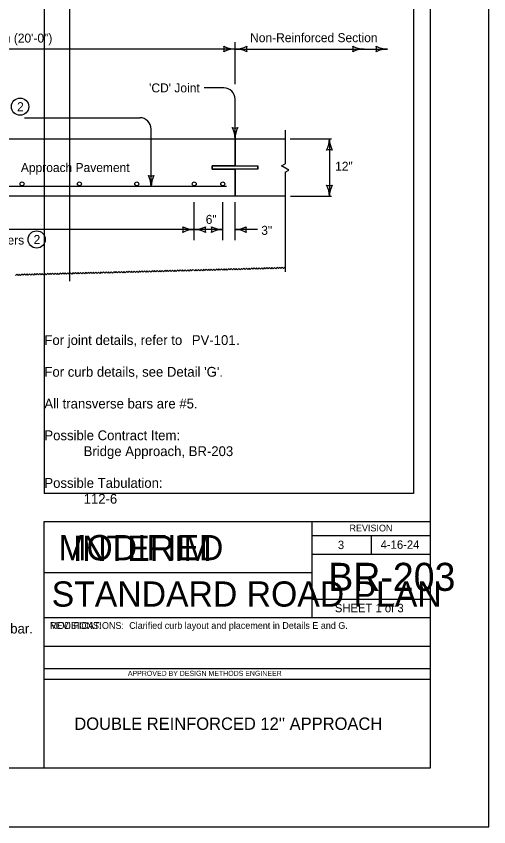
# Model space of a CAD drawing. Extents: x -2135039 to -2124495, y -2139046 to -2132546.
# Drawn here: x -2132538 to -2131695, y -2135130 to -2133685 of the extents above; entities that cross this region are included whole.
import ezdxf

# ---------------------------------------------------------------- set-up
doc = ezdxf.new("R2010")
doc.units = 0
for name, color, linetype in [('Barrier', 7, 'Continuous'), ('BridgeSuperStructureExisting', 7, 'Continuous'), ('Dimension', 7, 'Continuous'), ('dsnAlignmentCurveData', 7, 'Continuous'), ('dsnAlignmentStation', 7, 'Continuous'), ('dsnAlignmentTic', 7, 'Continuous'), ('dsnCellElements', 7, 'Continuous'), ('DsnShtPlotIdentification', 7, 'Continuous'), ('dsnStdLabel', 7, 'Continuous'), ('dsnStdLineWork', 7, 'Continuous'), ('dsnTextFinalPlan', 7, 'Continuous'), ('PhoEdgeShoulderPaved', 7, 'Continuous')]:
    doc.layers.add(name, color=color, linetype=linetype)

msp = doc.modelspace()

# ---------------------------------------------------------------- linework, layer by layer
at = {"layer": 'BridgeSuperStructureExisting'}
for p, q in [((-2132057.8, -2133888.2), (-2132057.8, -2133948.3)), ((-2132147.4, -2133952.1), (-2132147.4, -2133903.8)), ((-2132188.3, -2133957.8), (-2132188.3, -2133952.1)), ((-2132188.3, -2133952.1), (-2132106.5, -2133952.1)), ((-2132106.5, -2133957.8), (-2132188.3, -2133957.8)), ((-2132147.4, -2134006.1), (-2132147.4, -2133957.8)), ((-2132106.5, -2133952.1), (-2132106.5, -2133957.8)), ((-2132057.8, -2133963.4), (-2132057.8, -2134140.7)), ((-2132162.4, -2133989.1), (-2132604.1, -2133989.1))]:
    msp.add_line(p, q, dxfattribs=at)
msp.add_lwpolyline([(-2132057.8, -2133963.4), (-2132051.3, -2133959.6), (-2132064.4, -2133952), (-2132057.8, -2133948.3)], dxfattribs=at)
for centre in [(-2132530.7, -2133846.5), (-2132501.2, -2134083.3)]:
    msp.add_circle(centre, 15.4, dxfattribs=at)
for centre, radius, start, end in [((-2132146.2, -2133701.2), 42.5, 270, 298.0725), ((-2132146.2, -2133786.2), 42.5, 61.9275, 90), ((-2132110.6, -2133743.7), 16.4, 162.2666, 197.7334), ((-2132021.6, -2133903.9), 42.5, 331.9275, 360), ((-2132021.6, -2133903.9), 42.5, 331.9275, 360), ((-2131936.6, -2133903.9), 42.5, 180, 208.0725), ((-2131936.6, -2133903.9), 42.5, 180, 208.0725), ((-2131979.1, -2133939.6), 16.4, 72.2666, 107.7334), ((-2131979.1, -2133939.6), 16.4, 72.2666, 107.7334), ((-2131979.1, -2133970.6), 16.4, 252.2666, 287.7333), ((-2132021.6, -2134006.2), 42.5, 360, 28.0725), ((-2131936.6, -2134006.2), 42.5, 151.9275, 180)]:
    msp.add_arc(centre, radius, start, end, dxfattribs=at)
at = {"layer": 'Dimension'}
for p, q in [((-2132010.4, -2134585.9), (-2132010.4, -2134677.3)), ((-2132010.4, -2134610.9), (-2131799.4, -2134610.9)), ((-2131904.9, -2134610.9), (-2131904.9, -2134644.1)), ((-2132010.4, -2134644.1), (-2131799.4, -2134644.1)), ((-2132487.5, -2134677.3), (-2132010.4, -2134677.3)), ((-2132010.4, -2134677.3), (-2132010.4, -2134757.3)), ((-2131799.4, -2134725.1), (-2132010.4, -2134725.1)), ((-2132487.5, -2134757.3), (-2131799.4, -2134757.3)), ((-2132487.5, -2134808.3), (-2131799.4, -2134808.3)), ((-2132487.5, -2134848.3), (-2131799.4, -2134848.3)), ((-2132487.5, -2134867.3), (-2131799.4, -2134867.3))]:
    msp.add_line(p, q, dxfattribs=at)
msp.add_lwpolyline([(-2132487.5, -2134585.9), (-2131799.4, -2134585.9), (-2131799.4, -2135026), (-2132487.5, -2135026)], close=True, dxfattribs=at)
at = {"layer": 'dsnAlignmentStation'}
msp.add_lwpolyline([(-2134934.4, -2133016), (-2131799.4, -2133016), (-2131799.4, -2135026), (-2134934.4, -2135026)], close=True, dxfattribs=at)
at = {"layer": 'dsnCellElements'}
for centre, radius, start, end in [((-2132183, -2133743.6), 16.4, 342.2666, 17.7333), ((-2132147.4, -2133701.1), 42.5, 241.9275, 270), ((-2132147.4, -2133786.1), 42.5, 90, 118.0725), ((-2131953, -2133743.7), 16.4, 342.2666, 17.7333), ((-2131917.3, -2133701.2), 42.5, 241.9275, 270), ((-2131917.3, -2133786.2), 42.5, 90, 118.0725), ((-2131911.4, -2133743.7), 16.4, 342.2666, 17.7333), ((-2131875.8, -2133701.2), 42.5, 241.9275, 270), ((-2131875.8, -2133786.2), 42.5, 90, 118.0725), ((-2132147.4, -2133868.2), 16.4, 252.2666, 287.7333), ((-2132189.9, -2133903.8), 42.5, 360, 28.0725), ((-2132104.9, -2133903.8), 42.5, 151.9275, 180), ((-2132297, -2133953.4), 16.4, 252.2666, 287.7333), ((-2132339.5, -2133989.1), 42.5, 360, 28.0725), ((-2132254.5, -2133989.1), 42.5, 151.9275, 180), ((-2132255.9, -2134065.6), 16.4, 342.2666, 17.7333), ((-2132220.3, -2134023.1), 42.5, 241.9275, 270), ((-2132220.3, -2134023.1), 42.5, 270, 298.0725), ((-2132184.7, -2134065.6), 16.4, 162.2666, 197.7334), ((-2132204.8, -2134065.6), 16.4, 342.2666, 17.7333), ((-2132169.2, -2134023.1), 42.5, 241.9275, 270), ((-2132147.4, -2134023.1), 42.5, 270, 298.0725), ((-2132111.7, -2134065.6), 16.4, 162.2666, 197.7334), ((-2132220.3, -2134108.1), 42.5, 90, 118.0725), ((-2132220.3, -2134108.1), 42.5, 61.9275, 90), ((-2132169.2, -2134108.1), 42.5, 90, 118.0725), ((-2132147.4, -2134108.1), 42.5, 61.9275, 90)]:
    msp.add_arc(centre, radius, start, end, dxfattribs=at)
at = {"layer": 'dsnStdLabel'}
for p, q in [((-2133116, -2133743.6), (-2132147.4, -2133743.6)), ((-2132147.4, -2133806.3), (-2132147.4, -2133731.6)), ((-2132147.4, -2133743.7), (-2131875.8, -2133743.7)), ((-2132167.6, -2133813), (-2132202.5, -2133813)), ((-2132147.4, -2133903.8), (-2132147.4, -2133833.3)), ((-2132522.6, -2133866.2), (-2132317.2, -2133866.2)), ((-2132297, -2133989.1), (-2132297, -2133886.4)), ((-2132604.1, -2133903.8), (-2132147.4, -2133903.8)), ((-2132604.1, -2133903.8), (-2132147.4, -2133903.8)), ((-2132147.4, -2133903.8), (-2132147.4, -2133952.1)), ((-2132147.4, -2133903.8), (-2132057.8, -2133903.8)), ((-2132049.1, -2133903.9), (-2131975.2, -2133903.9)), ((-2131979.1, -2133903.9), (-2131979.1, -2134006.2)), ((-2132147.4, -2133952.1), (-2132188.3, -2133952.1)), ((-2132188.3, -2133952.1), (-2132188.3, -2133957.8)), ((-2132188.3, -2133952.1), (-2132188.3, -2133957.8)), ((-2132188.3, -2133957.8), (-2132147.4, -2133957.8)), ((-2132147.4, -2133957.8), (-2132147.4, -2134006.1)), ((-2132106.5, -2133957.8), (-2132106.5, -2133952.1)), ((-2132147.4, -2134006.1), (-2132604.1, -2134006.1)), ((-2132147.4, -2134006.1), (-2132604.1, -2134006.1)), ((-2132220.3, -2134084.7), (-2132220.3, -2134016.6)), ((-2132169.2, -2134084.7), (-2132169.2, -2134016.6)), ((-2132057.8, -2134006.1), (-2132147.4, -2134006.1)), ((-2132147.4, -2134084.7), (-2132147.4, -2134016.6)), ((-2132048.6, -2134006.2), (-2131975.2, -2134006.2)), ((-2132220.3, -2134065.6), (-2133043.1, -2134065.6)), ((-2132169.2, -2134065.6), (-2132220.3, -2134065.6)), ((-2132107.6, -2134065.6), (-2132147.4, -2134065.6))]:
    msp.add_line(p, q, dxfattribs=at)
for points in [[(-2132165.9, -2134136.7), (-2132167.1, -2134135.6), (-2132169.3, -2134137.9), (-2132171.6, -2134135.7), (-2132173.9, -2134138.1), (-2132176.2, -2134135.8), (-2132178.4, -2134138.2), (-2132180.7, -2134136), (-2132182.9, -2134138.3), (-2132185.3, -2134136.1), (-2132187.5, -2134138.4), (-2132189.8, -2134136.2), (-2132192.1, -2134138.5), (-2132194.4, -2134136.3), (-2132196.6, -2134138.7), (-2132198.9, -2134136.4), (-2132201.2, -2134138.8), (-2132203.5, -2134136.6), (-2132205.7, -2134138.9), (-2132208, -2134136.7), (-2132210.3, -2134139), (-2132212.6, -2134136.8), (-2132214.8, -2134139.1), (-2132217.1, -2134136.9), (-2132219.4, -2134139.3), (-2132220.5, -2134138.1)], [(-2132112.3, -2134135.3), (-2132113.4, -2134134.2), (-2132115.7, -2134136.5), (-2132118, -2134134.3), (-2132120.2, -2134136.6), (-2132122.5, -2134134.4), (-2132124.8, -2134136.8), (-2132127.1, -2134134.5), (-2132129.3, -2134136.9), (-2132131.6, -2134134.7), (-2132133.9, -2134137), (-2132136.2, -2134134.8), (-2132138.4, -2134137.1), (-2132140.7, -2134134.9), (-2132143, -2134137.2), (-2132145.3, -2134135), (-2132147.5, -2134137.4), (-2132149.8, -2134135.1), (-2132152.1, -2134137.5), (-2132154.4, -2134135.3), (-2132156.6, -2134137.6), (-2132158.9, -2134135.4), (-2132161.2, -2134137.7), (-2132163.5, -2134135.5), (-2132165.7, -2134137.8), (-2132166.9, -2134136.7)], [(-2132057.7, -2134133.9), (-2132058.8, -2134132.8), (-2132061, -2134135.1), (-2132063.4, -2134132.9), (-2132065.6, -2134135.2), (-2132067.9, -2134133), (-2132070.1, -2134135.3), (-2132072.5, -2134133.1), (-2132074.7, -2134135.5), (-2132077, -2134133.2), (-2132079.2, -2134135.6), (-2132081.6, -2134133.4), (-2132083.8, -2134135.7), (-2132086.1, -2134133.5), (-2132088.3, -2134135.8), (-2132090.7, -2134133.6), (-2132092.9, -2134135.9), (-2132095.2, -2134133.7), (-2132097.4, -2134136), (-2132099.8, -2134133.8), (-2132102, -2134136.2), (-2132104.3, -2134134), (-2132106.5, -2134136.3), (-2132108.9, -2134134.1), (-2132111.1, -2134136.4), (-2132112.3, -2134135.3)], [(-2132494.5, -2134145.3), (-2132495.7, -2134144.2), (-2132497.9, -2134146.5), (-2132500.2, -2134144.3), (-2132502.4, -2134146.6), (-2132504.8, -2134144.4), (-2132507, -2134146.7), (-2132509.3, -2134144.5), (-2132511.6, -2134146.9), (-2132513.9, -2134144.6), (-2132516.1, -2134147), (-2132518.4, -2134144.8), (-2132520.7, -2134147.1), (-2132523, -2134144.9), (-2132525.2, -2134147.2), (-2132527.5, -2134145), (-2132529.8, -2134147.3), (-2132532.1, -2134145.1), (-2132534.3, -2134147.5), (-2132536.6, -2134145.2), (-2132538.9, -2134147.6)], [(-2132439.9, -2134143.9), (-2132441.1, -2134142.7), (-2132443.3, -2134145.1), (-2132445.6, -2134142.9), (-2132447.8, -2134145.2), (-2132450.2, -2134143), (-2132452.4, -2134145.3), (-2132454.7, -2134143.1), (-2132456.9, -2134145.4), (-2132459.3, -2134143.2), (-2132461.5, -2134145.6), (-2132463.8, -2134143.3), (-2132466, -2134145.7), (-2132468.4, -2134143.5), (-2132470.6, -2134145.8), (-2132472.9, -2134143.6), (-2132475.1, -2134145.9), (-2132477.5, -2134143.7), (-2132479.7, -2134146), (-2132482, -2134143.8), (-2132484.3, -2134146.1), (-2132486.6, -2134143.9), (-2132488.8, -2134146.3), (-2132491.1, -2134144.1), (-2132493.3, -2134146.4), (-2132494.5, -2134145.3)], [(-2132385.3, -2134142.4), (-2132386.5, -2134141.3), (-2132388.7, -2134143.7), (-2132391, -2134141.4), (-2132393.2, -2134143.8), (-2132395.6, -2134141.6), (-2132397.8, -2134143.9), (-2132400.1, -2134141.7), (-2132402.3, -2134144), (-2132404.7, -2134141.8), (-2132406.9, -2134144.1), (-2132409.2, -2134141.9), (-2132411.4, -2134144.2), (-2132413.8, -2134142), (-2132416, -2134144.4), (-2132418.3, -2134142.2), (-2132420.5, -2134144.5), (-2132422.9, -2134142.3), (-2132425.1, -2134144.6), (-2132427.4, -2134142.4), (-2132429.6, -2134144.7), (-2132432, -2134142.5), (-2132434.2, -2134144.8), (-2132436.5, -2134142.6), (-2132438.7, -2134145), (-2132439.9, -2134143.9)], [(-2132330.7, -2134141), (-2132331.9, -2134139.9), (-2132334.1, -2134142.2), (-2132336.4, -2134140), (-2132338.6, -2134142.3), (-2132341, -2134140.1), (-2132343.2, -2134142.5), (-2132345.5, -2134140.2), (-2132347.7, -2134142.6), (-2132350.1, -2134140.4), (-2132352.3, -2134142.7), (-2132354.6, -2134140.5), (-2132356.8, -2134142.8), (-2132359.2, -2134140.6), (-2132361.4, -2134142.9), (-2132363.7, -2134140.7), (-2132365.9, -2134143.1), (-2132368.3, -2134140.8), (-2132370.5, -2134143.2), (-2132372.8, -2134141), (-2132375, -2134143.3), (-2132377.4, -2134141.1), (-2132379.6, -2134143.4), (-2132381.9, -2134141.2), (-2132384.1, -2134143.5), (-2132385.3, -2134142.4)], [(-2132276.1, -2134139.6), (-2132277.3, -2134138.5), (-2132279.5, -2134140.8), (-2132281.8, -2134138.6), (-2132284, -2134140.9), (-2132286.4, -2134138.7), (-2132288.6, -2134141), (-2132290.9, -2134138.8), (-2132293.1, -2134141.2), (-2132295.5, -2134138.9), (-2132297.7, -2134141.3), (-2132300, -2134139.1), (-2132302.2, -2134141.4), (-2132304.6, -2134139.2), (-2132306.8, -2134141.5), (-2132309.1, -2134139.3), (-2132311.3, -2134141.6), (-2132313.7, -2134139.4), (-2132315.9, -2134141.8), (-2132318.2, -2134139.5), (-2132320.4, -2134141.9), (-2132322.8, -2134139.7), (-2132325, -2134142), (-2132327.3, -2134139.8), (-2132329.5, -2134142.1), (-2132330.7, -2134141)], [(-2132221.5, -2134138.1), (-2132222.6, -2134137), (-2132224.9, -2134139.4), (-2132227.2, -2134137.2), (-2132229.4, -2134139.5), (-2132231.7, -2134137.3), (-2132234, -2134139.6), (-2132236.3, -2134137.4), (-2132238.5, -2134139.7), (-2132240.9, -2134137.5), (-2132243.1, -2134139.9), (-2132245.4, -2134137.6), (-2132247.6, -2134140), (-2132250, -2134137.8), (-2132252.2, -2134140.1), (-2132254.5, -2134137.9), (-2132256.7, -2134140.2), (-2132259.1, -2134138), (-2132261.3, -2134140.3), (-2132263.6, -2134138.1), (-2132265.8, -2134140.4), (-2132268.2, -2134138.2), (-2132270.4, -2134140.6), (-2132272.7, -2134138.3), (-2132274.9, -2134140.7), (-2132276.1, -2134139.6)]]:
    msp.add_lwpolyline(points, dxfattribs=at)
for centre in [(-2132167.6, -2133833.3), (-2132317.2, -2133886.4)]:
    msp.add_arc(centre, 20.2, 0, 90, dxfattribs=at)
at = {"layer": 'dsnStdLineWork'}
msp.add_lwpolyline([(-2135038.9, -2135130.5), (-2131694.9, -2135130.5), (-2131694.9, -2132546.5), (-2135038.9, -2132546.5)], close=True, dxfattribs=at)
at = {"layer": 'dsnTextFinalPlan'}
for centre in [(-2132527.2, -2133984.2), (-2132424.9, -2133984.2), (-2132322.6, -2133984.2), (-2132220.3, -2133984.2), (-2132169.2, -2133984.2)]:
    msp.add_circle(centre, 3.55, dxfattribs=at)
at = {"layer": 'PhoEdgeShoulderPaved'}
for p, q in [((-2132487.5, -2133066), (-2132487.5, -2134535.9)), ((-2131829.4, -2133066), (-2131829.4, -2134535.9)), ((-2132442.5, -2133166), (-2132442.5, -2134157.5)), ((-2131829.4, -2134535.9), (-2132487.5, -2134535.9))]:
    msp.add_line(p, q, dxfattribs=at)

# ---------------------------------------------------------------- texts
at = {"layer": 'Barrier'}
for s, p in [('For joint details, refer to ', (-2132487.4, -2134271.4)), ('PV-101', (-2132224.5, -2134271.4)), ('PV-101', (-2132224.5, -2134271.4)), ('.', (-2132145.2, -2134271.4)), ("For curb details, see Detail 'G'.", (-2132487.4, -2134328)), ('All transverse bars are #5.', (-2132487.4, -2134384.6)), ('Possible Contract Item:', (-2132487.4, -2134441.2)), ('Bridge Approach, BR-203', (-2132417.4, -2134469.5)), ('Possible Tabulation:', (-2132487.4, -2134526.1)), ('112-6', (-2132417.4, -2134554.4)), ('112-6', (-2132417.4, -2134554.4)), ('2" min. to 2 1/2" max. clear to bent bar.', (-2132912.2, -2134785.8))]:
    msp.add_text(s, height=17.5, dxfattribs=at).set_placement(p)
at = {"layer": 'Dimension'}
for s, height, p in [('REVISION', 12, (-2131943.4, -2134603.8)), ('3', 15, (-2131964.1, -2134635.3)), ('4-16-24', 15, (-2131887.8, -2134634.8)), ('BR-203', 50, (-2131981.2, -2134709.8)), ('STANDARD ROAD PLAN', 45.001, (-2132474.4, -2134737.9)), ('SHEET 1 of 3', 15, (-2131969.4, -2134747.9)), ('Clarified curb layout and placement in Details E and G.', 12, (-2132336.1, -2134777.5)), ('APPROVED BY DESIGN METHODS ENGINEER', 9.003, (-2132338.5, -2134861.4)), ("DOUBLE REINFORCED 12'' APPROACH", 22, (-2132434, -2134957.6))]:
    msp.add_text(s, height=height, dxfattribs=at).set_placement(p)
at = {"layer": 'dsnAlignmentCurveData'}
msp.add_text('REVISIONS:', height=12, dxfattribs=at).set_placement((-2132477.5, -2134777.6))
at = {"layer": 'dsnAlignmentTic'}
for s, height, p in [('MODIFIED', 45, (-2132462.4, -2134655.2)), ('MODIFICATIONS:', 12, (-2132477.5, -2134777.6))]:
    msp.add_text(s, height=height, dxfattribs=at).set_placement(p)
at = {"layer": 'DsnShtPlotIdentification'}
msp.add_text('INTERIM', height=45, dxfattribs=at).set_placement((-2132436.5, -2134656.3))
at = {"layer": 'dsnStdLabel'}
for s, p in [('Single Reinforced Section (20\'-0")', (-2132794.1, -2133732.2)), ('Non-Reinforced Section', (-2132120.5, -2133731.5)), ("'CD' Joint", (-2132300.6, -2133821)), ('2', (-2132536.1, -2133854.5)), ('Approach Pavement', (-2132529.3, -2133963)), ('12"', (-2131969, -2133960.8)), ('6"', (-2132199.7, -2134055.4)), ('3"', (-2132100.7, -2134075)), ('#5 Bars At 12" max. Centers', (-2132793.9, -2134092.4)), ('2', (-2132506.6, -2134091.3))]:
    msp.add_text(s, height=16, dxfattribs=at).set_placement(p)

doc.saveas('drawing.dxf')
